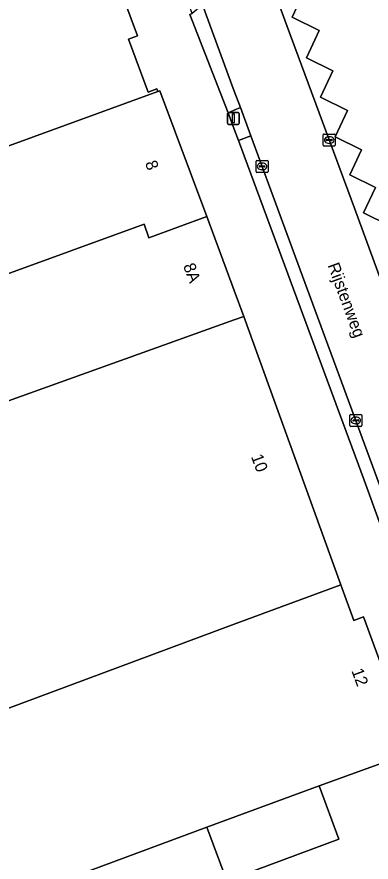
# Model space of a CAD drawing. Extents: x 158086 to 159499, y 382904 to 383981.
# Drawn here: x 158981.9 to 159011.4, y 383019.4 to 383089.9 of the extents above; entities that cross this region are included whole.
import ezdxf

# ---------------------------------------------------------------- set-up
doc = ezdxf.new("R2010")
doc.units = 0
for name, color, linetype in [('IMGEO_Erf', 7, 'Continuous'), ('IMGEO_Kolk', 7, 'Continuous'), ('IMGEO_Lichtmast', 7, 'Continuous'), ('IMGEO_Openbare_ruimte_label', 7, 'Continuous'), ('IMGEO_Pand', 7, 'Continuous'), ('IMGEO_Pand_nummerreeks', 7, 'Continuous'), ('IMGEO_Parkeervlak_open', 7, 'Continuous'), ('IMGEO_Rijbaan_lokaal_open', 7, 'Continuous'), ('IMGEO_Voetpad_open', 7, 'Continuous')]:
    doc.layers.add(name, color=color, linetype=linetype)

msp = doc.modelspace()

# ---------------------------------------------------------------- linework, layer by layer
at = {"layer": 'IMGEO_Erf'}
for points in [[(159013.433, 383044.02), (159010.822, 383051.232), (159000.349, 383079.556), (159000, 383080.506), (158999.501, 383081.865), (158996.298, 383090.065), (158996.488, 383090.145), (158989.898, 383108.183), (158987.936, 383113.554), (158980.634, 383133.543)], [(158984.812, 383107.476), (158991.945, 383088.285), (158991.178, 383088), (158992.822, 383083.576), (158993.553, 383083.847), (158993.633, 383083.633), (158993.805, 383083.696), (158997.708, 383073.198), (158999.994, 383067.047), (159000.787, 383064.87), (159008.873, 383042.495), (159009.95, 383039.516), (159010.762, 383039.814), (159014.891, 383028.571), (159007.077, 383025.716), (159008.724, 383021.275), (158999.382, 383017.81), (158997.721, 383022.286), (158979.226, 383015.425)]]:
    msp.add_lwpolyline(points, dxfattribs=at)
at = {"layer": 'IMGEO_Kolk'}
for p, q in [((159007.409, 383079.162), (159007.409, 383080.014)), ((159007.484, 383080.088), (159008.336, 383080.088)), ((159007.668, 383079.582), (159007.668, 383079.594)), ((159008.106, 383079.545), (159007.708, 383079.545)), ((159007.711, 383079.631), (159008.109, 383079.631)), ((159007.897, 383079.868), (159007.922, 383079.868)), ((159008.152, 383079.594), (159008.152, 383079.582)), ((159008.41, 383080.014), (159008.41, 383079.162)), ((159008.336, 383079.088), (159007.484, 383079.088)), ((159007.92, 383079.308), (159007.895, 383079.308)), ((159001.814, 383076.961), (159001.814, 383077.813)), ((159001.889, 383077.887), (159002.741, 383077.887)), ((159002.073, 383077.381), (159002.073, 383077.393)), ((159002.511, 383077.344), (159002.113, 383077.344)), ((159002.116, 383077.43), (159002.514, 383077.43)), ((159002.302, 383077.667), (159002.327, 383077.667)), ((159002.557, 383077.393), (159002.557, 383077.381)), ((159002.815, 383077.813), (159002.815, 383076.961)), ((159002.741, 383076.887), (159001.889, 383076.887)), ((159002.325, 383077.107), (159002.3, 383077.107)), ((159009.624, 383055.776), (159009.624, 383056.628)), ((159009.699, 383056.702), (159010.551, 383056.702)), ((159009.883, 383056.196), (159009.883, 383056.208)), ((159010.321, 383056.159), (159009.923, 383056.159)), ((159009.926, 383056.245), (159010.324, 383056.245)), ((159010.112, 383056.482), (159010.137, 383056.482)), ((159010.367, 383056.208), (159010.367, 383056.196)), ((159010.625, 383056.628), (159010.625, 383055.776)), ((159010.551, 383055.702), (159009.699, 383055.702)), ((159010.135, 383055.922), (159010.11, 383055.922))]:
    msp.add_line(p, q, dxfattribs=at)
for points in [[(159007.409, 383079.162), (159007.409, 383080.014)], [(159007.484, 383080.088), (159008.336, 383080.088)], [(159008.41, 383080.014), (159008.41, 383079.162)], [(159008.336, 383079.088), (159007.484, 383079.088)], [(159001.814, 383076.961), (159001.814, 383077.813)], [(159001.889, 383077.887), (159002.741, 383077.887)], [(159002.815, 383077.813), (159002.815, 383076.961)], [(159002.741, 383076.887), (159001.889, 383076.887)], [(159009.624, 383055.776), (159009.624, 383056.628)], [(159009.699, 383056.702), (159010.551, 383056.702)], [(159010.625, 383056.628), (159010.625, 383055.776)], [(159010.551, 383055.702), (159009.699, 383055.702)]]:
    msp.add_lwpolyline(points, dxfattribs=at)
for centre, radius, start, end in [((159007.486, 383080.012), 0.0765, 91.55205, 178.44795), ((159007.486, 383080.012), 0.0765, 91.55205, 178.44795), ((159007.708, 383079.591), 0.0403, 85.87752, 175.75265), ((159007.705, 383079.581), 0.0366, 178.93798, 274.71019), ((159008.109, 383079.588), 0.043, 264.86636, 352.45326), ((159008.113, 383079.593), 0.0386, 1.73085, 96.63898), ((159008.334, 383080.012), 0.0765, 1.55205, 88.44795), ((159008.334, 383080.012), 0.0765, 1.55205, 88.44795), ((159007.486, 383079.164), 0.0765, 181.55205, 268.44795), ((159007.486, 383079.164), 0.0765, 181.55205, 268.44795), ((159008.334, 383079.164), 0.0765, 271.55205, 358.44795), ((159008.334, 383079.164), 0.0765, 271.55205, 358.44795), ((159001.891, 383077.811), 0.0765, 91.55205, 178.44795), ((159001.891, 383077.811), 0.0765, 91.55205, 178.44795), ((159002.113, 383077.39), 0.0403, 85.87752, 175.75265), ((159002.11, 383077.38), 0.0366, 178.93798, 274.71019), ((159002.514, 383077.387), 0.043, 264.86636, 352.45326), ((159002.518, 383077.392), 0.0386, 1.73085, 96.63898), ((159002.739, 383077.811), 0.0765, 1.55205, 88.44795), ((159002.739, 383077.811), 0.0765, 1.55205, 88.44795), ((159001.891, 383076.963), 0.0765, 181.55205, 268.44795), ((159001.891, 383076.963), 0.0765, 181.55205, 268.44795), ((159002.739, 383076.963), 0.0765, 271.55205, 358.44795), ((159002.739, 383076.963), 0.0765, 271.55205, 358.44795), ((159009.701, 383056.626), 0.0765, 91.55205, 178.44795), ((159009.701, 383056.626), 0.0765, 91.55205, 178.44795), ((159009.923, 383056.205), 0.0403, 85.87752, 175.75265), ((159009.92, 383056.195), 0.0366, 178.93798, 274.71019), ((159010.324, 383056.202), 0.043, 264.86636, 352.45326), ((159010.328, 383056.207), 0.0386, 1.73085, 96.63898), ((159010.549, 383056.626), 0.0765, 1.55205, 88.44795), ((159010.549, 383056.626), 0.0765, 1.55205, 88.44795), ((159009.701, 383055.778), 0.0765, 181.55205, 268.44795), ((159009.701, 383055.778), 0.0765, 181.55205, 268.44795), ((159010.549, 383055.778), 0.0765, 271.55205, 358.44795), ((159010.549, 383055.778), 0.0765, 271.55205, 358.44795)]:
    msp.add_arc(centre, radius, start, end, dxfattribs=at)
for centre, major_axis, ratio, start_param, end_param in [((159007.896, 383079.588), (-0.387, 0.002), 0.722429, 4.712389, 7.853982), ((159007.921, 383079.588), (-0.39, 0.002), 0.717154, 1.570796, 4.712389), ((159002.301, 383077.387), (-0.387, 0.002), 0.722429, 4.712389, 7.853982), ((159002.326, 383077.387), (-0.39, 0.002), 0.717154, 1.570796, 4.712389), ((159010.111, 383056.202), (-0.387, 0.002), 0.722429, 4.712389, 7.853982), ((159010.136, 383056.202), (-0.39, 0.002), 0.717154, 1.570796, 4.712389)]:
    msp.add_ellipse(centre, major_axis=major_axis, ratio=ratio, start_param=start_param, end_param=end_param, dxfattribs=at)
at = {"layer": 'IMGEO_Lichtmast'}
for p, q in [((158999.421, 383080.996), (158999.421, 383081.796)), ((158999.421, 383081.796), (158999.421, 383080.996)), ((158999.521, 383081.896), (159000.311, 383081.896)), ((159000.311, 383081.896), (158999.521, 383081.896)), ((159000.411, 383081.796), (159000.411, 383080.996)), ((159000.411, 383080.996), (159000.411, 383081.796)), ((159000.311, 383080.896), (158999.521, 383080.896)), ((158999.521, 383080.896), (159000.311, 383080.896))]:
    msp.add_line(p, q, dxfattribs=at)
msp.add_lwpolyline([(158999.841, 383081.771), (158999.991, 383081.771), (158999.991, 383081.021), (158999.841, 383081.021), (158999.841, 383081.771)], dxfattribs=at)
for centre, start, end in [((158999.521, 383081.796), 90, 180), ((158999.521, 383081.796), 90, 180), ((159000.311, 383081.796), 0, 90), ((159000.311, 383081.796), 360, 90), ((158999.521, 383080.996), 180, 270), ((158999.521, 383080.996), 180, 270), ((159000.311, 383080.996), 270, 0), ((159000.311, 383080.996), 270, 0)]:
    msp.add_arc(centre, 0.1, start, end, dxfattribs=at)
at = {"layer": 'IMGEO_Pand'}
for points in [[(158984.812, 383107.476), (158984.156, 383107.233), (158982.521, 383111.63), (158956.46, 383101.94), (158945.753, 383098.203), (158957.707, 383070.476), (158967.848, 383074.237), (158993.633, 383083.633), (158993.553, 383083.847), (158992.822, 383083.576), (158991.178, 383088), (158991.945, 383088.285)], [(158961.725, 383061.354), (158992.481, 383072.57), (158992.892, 383071.443), (158997.708, 383073.198), (158993.805, 383083.696), (158993.633, 383083.633), (158967.848, 383074.237), (158957.707, 383070.476)], [(158965.753, 383052.208), (158971.71, 383054.452), (159000, 383064.588), (159000.787, 383064.87), (158999.994, 383067.047), (158997.708, 383073.198), (158992.892, 383071.443), (158992.481, 383072.57), (158961.725, 383061.354)], [(158965.753, 383052.208), (158975.363, 383030.024), (159000, 383039.204), (159008.873, 383042.495), (159000.787, 383064.87), (159000, 383064.588), (158971.71, 383054.452)], [(159010.762, 383039.814), (159009.95, 383039.516), (159008.873, 383042.495), (159000, 383039.204), (158975.363, 383030.024), (158979.832, 383019.706), (158979.916, 383019.512), (158979.977, 383019.372), (158979.226, 383015.425), (158997.721, 383022.286), (159007.077, 383025.716), (159014.891, 383028.571)], [(159007.077, 383025.716), (158997.721, 383022.286), (158999.382, 383017.81), (159008.724, 383021.275)]]:
    msp.add_lwpolyline(points, close=True, dxfattribs=at)
at = {"layer": 'IMGEO_Parkeervlak_open'}
msp.add_lwpolyline([(159005.826, 383092.009), (159004.811, 383089.848), (159007.073, 383088.717), (159006.008, 383086.448), (159008.213, 383085.346), (159007.189, 383083.165), (159009.435, 383082.042), (159008.409, 383079.856), (159010.595, 383078.763), (159009.624, 383076.695), (159011.765, 383075.625), (159010.773, 383073.512), (159012.957, 383072.42)], dxfattribs=at)
at = {"layer": 'IMGEO_Rijbaan_lokaal_open'}
for points in [[(158991.444, 383136.082), (158991.322, 383136.048), (158982.077, 383133.078), (158982.594, 383131.636), (158985.382, 383123.536), (158988.889, 383113.943), (158990.854, 383108.568), (158994.259, 383099.253), (158997.353, 383090.855), (159000, 383083.673), (159000.505, 383082.302), (159001.376, 383079.933), (159005.874, 383067.711), (159010.659, 383054.753), (159014.295, 383044.868), (159019.666, 383030.258), (159022.721, 383022.013), (159024.083, 383018.337), (159025.62, 383014.093), (159027.294, 383008.889)], [(159024.745, 383033.951), (159017.762, 383052.749), (159010.016, 383073.897), (159004.399, 383089.064), (159000.486, 383099.77), (159000, 383101.106), (158993.547, 383118.852), (158989.507, 383130.115), (158989.496, 383130.166)], [(159000.486, 383099.77), (159004.399, 383089.064), (159010.016, 383073.897), (159017.762, 383052.749), (159024.745, 383033.951), (159029.515, 383020.822), (159032.675, 383022.195), (159032.687, 383022.202)], [(159012.957, 383072.42), (159010.773, 383073.512), (159011.765, 383075.625), (159009.624, 383076.695), (159010.595, 383078.763), (159008.409, 383079.856), (159009.435, 383082.042), (159007.189, 383083.165), (159008.213, 383085.346), (159006.008, 383086.448), (159007.073, 383088.717), (159004.811, 383089.848), (159005.826, 383092.009)]]:
    msp.add_lwpolyline(points, dxfattribs=at)
at = {"layer": 'IMGEO_Voetpad_open'}
for points in [[(159000.505, 383082.302), (159000, 383083.673), (158997.353, 383090.855), (158996.488, 383090.145), (158996.298, 383090.065), (158999.501, 383081.865), (159000, 383082.082)], [(159000.505, 383082.302), (159000, 383082.082), (158999.501, 383081.865), (159000, 383080.506), (159000.349, 383079.556), (159001.376, 383079.933)], [(159001.376, 383079.933), (159000.349, 383079.556), (159010.822, 383051.232), (159013.433, 383044.02), (159018.685, 383029.891), (159019.666, 383030.258), (159014.295, 383044.868), (159010.659, 383054.753), (159005.874, 383067.711)]]:
    msp.add_lwpolyline(points, close=True, dxfattribs=at)

# ---------------------------------------------------------------- texts
at = {"layer": 'IMGEO_Openbare_ruimte_label'}
msp.add_text('Rijstenweg', height=1, rotation=290.17394, dxfattribs=at).set_placement((159007.761, 383069.147))
at = {"layer": 'IMGEO_Pand_nummerreeks'}
for s, rotation, p in [('8', 290.39361, (158992.546, 383077.669)), ('8A', 290.34555, (158995.726, 383069.108)), ('10', 290.4845, (159001.379, 383053.185)), ('12', 290.1679, (159009.747, 383035.326))]:
    msp.add_text(s, height=1, rotation=rotation, dxfattribs=at).set_placement(p)

doc.saveas('drawing.dxf')
